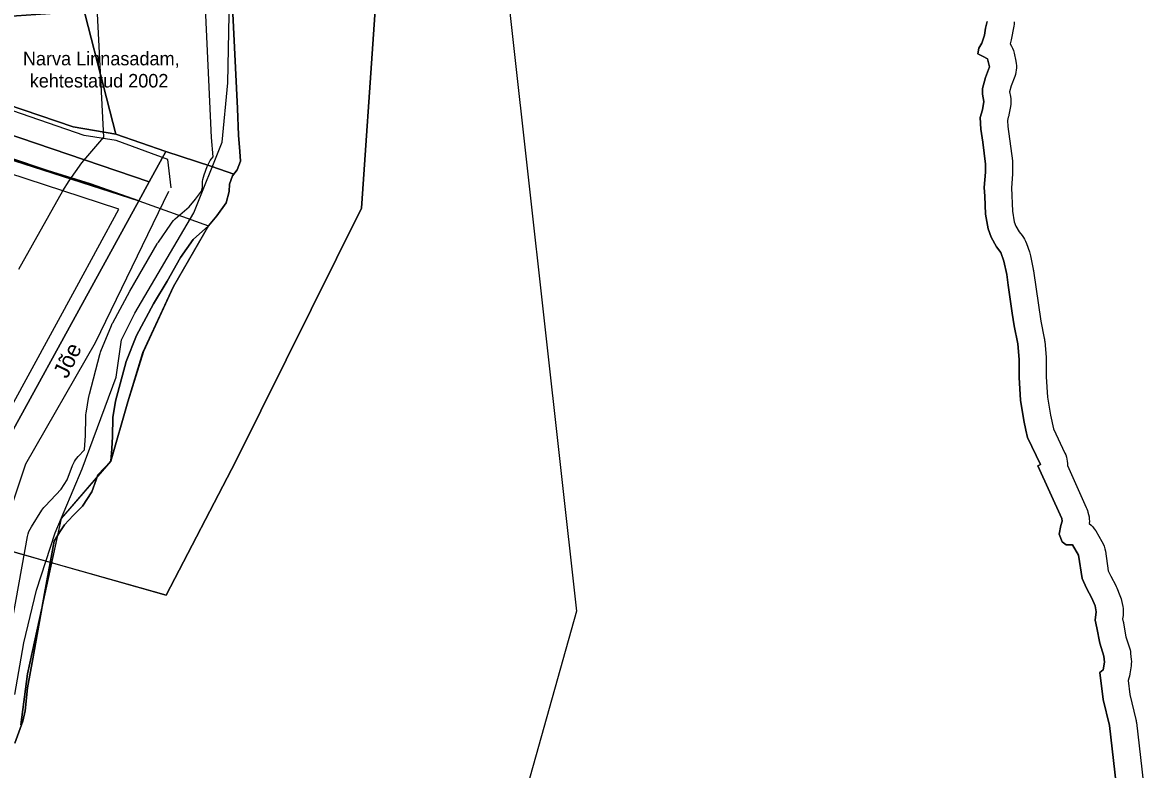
# Model space of a CAD drawing. Extents: x 728832 to 739469, y 6586263 to 6599699.
# Drawn here: x 738858.8 to 739275, y 6589907.2 to 6590183.4 of the extents above; entities that cross this region are included whole.
import ezdxf

# ---------------------------------------------------------------- set-up
doc = ezdxf.new("R2010")
doc.units = 0
for name, color, linetype in [('a_kalda_ekv', 7, 'Continuous'), ('a_kalda_veekaitsev', 7, 'Continuous'), ('a_looduskaitse_voond', 7, 'Continuous'), ('a_piir', 7, 'Continuous'), ('a_veekogu_piir', 7, 'Continuous'), ('dp_hoonestus', 7, 'Continuous'), ('v_dp_kehtiv', 7, 'Continuous'), ('v_dp_kehtiv_tekst', 7, 'Continuous'), ('v_dp_kontaktvoond', 7, 'Continuous'), ('v_dp_tanav_tekst', 7, 'Continuous'), ('v_olol_transp_jjt', 7, 'Continuous')]:
    doc.layers.add(name, color=color, linetype=linetype)

msp = doc.modelspace()

# ---------------------------------------------------------------- linework, layer by layer
at = {"layer": 'a_kalda_ekv'}
msp.add_lwpolyline([(738857.47, 6590092.24), (738873.8, 6590121.13), (738876.13, 6590124.85), (738880.71, 6590131.52), (738888.96, 6590141.03), (738886.6, 6590186.61), (738884.94, 6590197.52), (738885.19, 6590218.49), (738887.23, 6590228.8), (738886.16, 6590230.66), (738878.79, 6590251.31), (738871.89, 6590262.03), (738871.04, 6590263.97), (738863.76, 6590273.78), (738857.24, 6590285.58)], dxfattribs=at)
at = {"layer": 'a_kalda_veekaitsev'}
for points in [[(738850.87, 6589939.22), (738860.7, 6589993.36), (738860.92, 6589994.29), (738861.22, 6589995.21), (738861.62, 6589996.09), (738862.09, 6589996.92), (738865.96, 6590003.03), (738866.34, 6590003.58), (738866.75, 6590004.1), (738867.2, 6590004.6), (738873.13, 6590010.78), (738875.4, 6590014.34), (738877.35, 6590019.59), (738877.66, 6590020.32), (738878.02, 6590021.03), (738878.43, 6590021.7), (738878.9, 6590022.34), (738879.42, 6590022.94), (738881.73, 6590025.41), (738882.11, 6590030.73), (738882.2, 6590037.42), (738882.22, 6590037.94), (738882.27, 6590038.46), (738882.34, 6590038.97), (738883.39, 6590045.11), (738883.45, 6590045.4), (738883.51, 6590045.69), (738883.58, 6590045.98), (738887.46, 6590060.63), (738887.57, 6590061.03), (738887.71, 6590061.43), (738887.85, 6590061.82), (738891.72, 6590071.38), (738891.86, 6590071.72), (738892.02, 6590072.06), (738892.19, 6590072.39), (738898.52, 6590084.08), (738908.69, 6590101.55), (738908.81, 6590101.77), (738908.95, 6590101.98), (738909.09, 6590102.19), (738913.67, 6590108.86), (738914.18, 6590109.53), (738914.74, 6590110.16), (738915.35, 6590110.73), (738920.46, 6590115.18), (738922.83, 6590118.01), (738925.01, 6590121.06), (738925.36, 6590122.33), (738925.38, 6590123.74), (738925.43, 6590124.57), (738925.55, 6590125.39), (738925.74, 6590126.2), (738925.99, 6590127), (738927.15, 6590130.16), (738927.47, 6590130.91), (738927.84, 6590131.64), (738928.28, 6590132.34), (738928.77, 6590133), (738929.34, 6590133.71), (738928.77, 6590140.91), (738926.54, 6590188.74)], [(738936.53, 6590189.2), (738938.37, 6590151.54), (738938.74, 6590141.69), (738939.18, 6590135.73), (738939.49, 6590132.15), (738938.28, 6590128.86), (738936.54, 6590126.71), (738935.38, 6590123.55), (738935.33, 6590120.89), (738934.18, 6590116.71), (738930.75, 6590111.88), (738927.61, 6590108.15), (738921.91, 6590103.19), (738917.33, 6590096.52), (738912.29, 6590087.76), (738907.32, 6590079.32), (738900.99, 6590067.63), (738897.13, 6590058.07), (738893.25, 6590043.42), (738892.2, 6590037.28), (738892.1, 6590030.3), (738891.83, 6590025.75), (738891.45, 6590021.17), (738886.73, 6590016.11), (738886.1, 6590014.31), (738884.41, 6590009.86), (738881.03, 6590004.57), (738877.54, 6590001.07), (738874.41, 6589997.67), (738872.68, 6589995.03), (738870.54, 6589991.57), (738867, 6589972.26), (738862.7, 6589948.13), (738860.71, 6589937.44), (738859.77, 6589928.86), (738858.93, 6589925.05), (738855.98, 6589916.9)], [(739265.09, 6589887.82), (739260.98, 6589923.4), (739258.66, 6589933.13), (739257.42, 6589943.08), (739258.64, 6589944), (739259.06, 6589946.92), (739258.84, 6589949.11), (739257.33, 6589953.89), (739256.33, 6589959.53), (739255.66, 6589962.39), (739256.06, 6589965.48), (739255.61, 6589967.69), (739254.43, 6589970.5), (739252.45, 6589974.25), (739250.84, 6589977.75), (739249.54, 6589986.39), (739247.23, 6589990.31), (739244.92, 6589990.21), (739243.51, 6589991.42), (739242.4, 6589994.23), (739243.01, 6589997.45), (739243.51, 6589999.06), (739243.28, 6590000), (739234.48, 6590019.44), (739235.41, 6590019.9), (739230.64, 6590029.89), (739230.05, 6590032.66), (739229.33, 6590036.28), (739228.04, 6590043.73), (739227.55, 6590052.13), (739227.56, 6590058.75), (739227.05, 6590064.58), (739225.65, 6590071.21), (739224.94, 6590075.86), (739223.48, 6590086.24), (739222.94, 6590090.16), (739221.93, 6590095.19), (739220.8, 6590098.37), (739219.18, 6590100.41), (739217.2, 6590103.95), (739216.05, 6590107.13), (739215.08, 6590112.51), (739214.83, 6590119.12), (739214.63, 6590122.39), (739215.07, 6590128.04), (739215.13, 6590130.96), (739214.09, 6590139.18), (739213.39, 6590143.98), (739213.1, 6590148.21), (739213.92, 6590151.07), (739214.51, 6590154.19), (739214.01, 6590156.83), (739213.96, 6590158.99), (739215.06, 6590163.04), (739216.52, 6590166.93), (739215.86, 6590169.97), (739214.21, 6590170.78), (739212.26, 6590171.77), (739212.65, 6590173.9), (739213.7, 6590175.76), (739214.77, 6590178.7), (739215.15, 6590181.33), (739215.69, 6590183.77)], [(739225.69, 6590183.66), (739225.64, 6590182.82), (739225.53, 6590182), (739224.61, 6590176.93), (739224.51, 6590176.43), (739224.38, 6590175.94), (739224.23, 6590175.45), (739224.7, 6590174.66), (739225.09, 6590173.83), (739225.4, 6590172.97), (739225.64, 6590172.08), (739226.29, 6590169.04), (739226.43, 6590168.24), (739226.5, 6590167.43), (739226.51, 6590166.61), (739226.45, 6590165.8), (739226.33, 6590165), (739226.14, 6590164.21), (739225.89, 6590163.44), (739224.59, 6590159.97), (739224.01, 6590157.8), (739224.34, 6590156.03), (739224.47, 6590155.11), (739224.51, 6590154.17), (739224.47, 6590153.24), (739224.33, 6590152.32), (739223.74, 6590149.2), (739223.68, 6590148.91), (739223.61, 6590148.62), (739223.53, 6590148.33), (739223.2, 6590147.15), (739223.34, 6590144.98), (739225.04, 6590132.28), (739225.1, 6590131.78), (739225.13, 6590131.27), (739225.13, 6590130.75), (739225.07, 6590127.84), (739225.06, 6590127.65), (739225.05, 6590127.46), (739225.04, 6590127.26), (739224.65, 6590122.23), (739225.04, 6590113.63), (739225.74, 6590109.74), (739226.33, 6590108.12), (739227.51, 6590106), (739228.63, 6590104.59), (739229.11, 6590103.93), (739229.54, 6590103.22), (739229.91, 6590102.48), (739230.22, 6590101.72), (739231.35, 6590098.54), (739231.5, 6590098.09), (739231.63, 6590097.63), (739231.73, 6590097.16), (739232.74, 6590092.14), (739232.78, 6590091.95), (739232.81, 6590091.77), (739232.84, 6590091.58), (739235.5, 6590072.95), (739236.83, 6590066.64), (739236.91, 6590066.24), (739236.97, 6590065.85), (739237.01, 6590065.45), (739237.52, 6590059.63), (739237.54, 6590059.33), (739237.56, 6590059.04), (739237.56, 6590058.74), (739237.55, 6590052.41), (739237.99, 6590044.87), (739239.16, 6590038.14), (739240.19, 6590033.1), (739244.44, 6590024.21), (739244.75, 6590023.48), (739245.01, 6590022.72), (739245.2, 6590021.94), (739245.34, 6590021.16), (739245.4, 6590020.36), (739245.41, 6590019.56), (739252.39, 6590004.12), (739252.63, 6590003.55), (739252.83, 6590002.97), (739252.99, 6590002.38), (739253.22, 6590001.44), (739253.39, 6590000.62), (739253.48, 6589999.79), (739253.51, 6589998.96), (739253.47, 6589998.13), (739254.15, 6589997.53), (739254.78, 6589996.87), (739255.35, 6589996.15), (739255.85, 6589995.39), (739258.16, 6589991.47), (739258.6, 6589990.62), (739258.96, 6589989.73), (739259.24, 6589988.82), (739259.43, 6589987.88), (739260.52, 6589980.64), (739261.42, 6589978.68), (739263.27, 6589975.17), (739263.4, 6589974.91), (739263.53, 6589974.65), (739263.65, 6589974.38), (739264.83, 6589971.58), (739265.06, 6589970.96), (739265.26, 6589970.33), (739265.41, 6589969.69), (739265.86, 6589967.48), (739265.99, 6589966.66), (739266.06, 6589965.83), (739266.05, 6589965), (739265.98, 6589964.17), (739265.81, 6589962.9), (739266.06, 6589961.81), (739266.1, 6589961.64), (739266.14, 6589961.46), (739266.17, 6589961.29), (739267.06, 6589956.29), (739268.38, 6589952.12), (739268.56, 6589951.46), (739268.7, 6589950.79), (739268.79, 6589950.11), (739269.01, 6589947.92), (739269.06, 6589947.11), (739269.04, 6589946.3), (739268.96, 6589945.49), (739268.54, 6589942.58), (739268.38, 6589941.75), (739268.16, 6589940.93), (739267.86, 6589940.14), (739268.52, 6589934.92), (739270.71, 6589925.72), (739270.8, 6589925.33), (739270.86, 6589924.94), (739270.92, 6589924.55), (739275.02, 6589888.97)]]:
    msp.add_lwpolyline(points, dxfattribs=at)
at = {"layer": 'a_looduskaitse_voond'}
msp.add_lwpolyline([(738848.75, 6590030.6), (738861.66, 6590054.1), (738878.87, 6590085.71), (738894.43, 6590114.34), (738853.38, 6590127.75)], dxfattribs=at)
at = {"layer": 'a_piir'}
for points in [[(738618.75, 6590380.33), (738607.64, 6590378.6), (738566.13, 6590357.93), (738559.92, 6590348.55), (738569.64, 6590329.09), (738573.98, 6590313.62), (738617.27, 6590348.72), (738629.02, 6590355.8), (738689.32, 6590229.61), (738675.68, 6590194.79), (738695.6, 6590176.04), (738728.46, 6590145.13), (738765.47, 6590163.01), (738835.3, 6590138.74), (738883.93, 6590123.77), (738901.84, 6590117.49), (738905.68, 6590124.48), (738762.03, 6590173.28), (738749.36, 6590180.65), (738732, 6590194.18), (738718.81, 6590211.81), (738712.34, 6590224.93), (738650.22, 6590356.38), (738637.19, 6590372.44)], [(738843.25, 6590304.19), (738738, 6590297.5), (738693.54, 6590289.26), (738721.83, 6590229.41), (738728.22, 6590217.92), (738736.09, 6590207.4), (738745.32, 6590197.99), (738755.65, 6590189.94), (738767, 6590183.31), (738779.12, 6590178.25), (738877.58, 6590144.8), (738893.32, 6590142.09), (738861.55, 6590265.91)]]:
    msp.add_lwpolyline(points, close=True, dxfattribs=at)
for points in [[(738861.55, 6590265.91), (738893.32, 6590142.09), (738911.86, 6590135.74), (738928.88, 6590130.08), (738937.06, 6590127.35), (738938.28, 6590128.86), (738939.49, 6590132.15), (738939.18, 6590135.73), (738938.74, 6590141.69), (738938.37, 6590151.54), (738936.53, 6590189.2)], [(738762.03, 6590173.28), (738905.68, 6590124.48), (738911.86, 6590135.74), (738893.32, 6590142.09), (738877.58, 6590144.8), (738779.12, 6590178.25)], [(738833.77, 6589993.69), (738901.84, 6590117.49), (738883.93, 6590123.77), (738835.3, 6590138.74)], [(738858.18, 6589923.69), (738860.66, 6589942.56), (738873.24, 6589999.99), (738891.45, 6590021.17), (738897.74, 6590043.18), (738903.36, 6590061.39), (738914.63, 6590085.72), (738927.61, 6590108.15), (738930.75, 6590111.88), (738934.15, 6590116.67), (738935.33, 6590120.89), (738935.38, 6590123.55), (738936.54, 6590126.71), (738937.06, 6590127.35), (738928.88, 6590130.08), (738911.86, 6590135.74), (738905.68, 6590124.48), (738901.84, 6590117.49), (738833.77, 6589993.69)]]:
    msp.add_lwpolyline(points, dxfattribs=at)
at = {"layer": 'a_veekogu_piir'}
for points in [[(738855.98, 6589916.9), (738858.93, 6589925.05), (738859.77, 6589928.86), (738860.71, 6589937.44), (738862.7, 6589948.13), (738867, 6589972.26), (738870.54, 6589991.57), (738872.68, 6589995.03), (738874.41, 6589997.67), (738877.54, 6590001.07), (738881.03, 6590004.57), (738884.41, 6590009.86), (738886.1, 6590014.31), (738886.73, 6590016.11), (738891.45, 6590021.17), (738891.83, 6590025.75), (738892.1, 6590030.3), (738892.2, 6590037.28), (738893.25, 6590043.42), (738897.13, 6590058.07), (738900.99, 6590067.63), (738907.32, 6590079.32), (738912.29, 6590087.76), (738917.33, 6590096.52), (738921.91, 6590103.19), (738927.61, 6590108.15), (738930.75, 6590111.88), (738934.18, 6590116.71), (738935.33, 6590120.89), (738935.38, 6590123.55), (738936.54, 6590126.71), (738938.28, 6590128.86), (738939.49, 6590132.15), (738939.18, 6590135.73), (738938.74, 6590141.69), (738938.37, 6590151.54), (738936.53, 6590189.2)], [(739215.69, 6590183.77), (739215.15, 6590181.33), (739214.77, 6590178.7), (739213.7, 6590175.76), (739212.65, 6590173.9), (739212.26, 6590171.77), (739214.21, 6590170.78), (739215.86, 6590169.97), (739216.52, 6590166.93), (739215.06, 6590163.04), (739213.96, 6590158.99), (739214.01, 6590156.83), (739214.51, 6590154.19), (739213.92, 6590151.07), (739213.1, 6590148.21), (739213.39, 6590143.98), (739214.09, 6590139.18), (739215.13, 6590130.96), (739215.07, 6590128.04), (739214.63, 6590122.39), (739214.83, 6590119.12), (739215.08, 6590112.51), (739216.05, 6590107.13), (739217.2, 6590103.95), (739219.18, 6590100.41), (739220.8, 6590098.37), (739221.93, 6590095.19), (739222.94, 6590090.16), (739223.48, 6590086.24), (739224.94, 6590075.86), (739225.65, 6590071.21), (739227.05, 6590064.58), (739227.56, 6590058.75), (739227.55, 6590052.13), (739228.04, 6590043.73), (739229.33, 6590036.28), (739230.05, 6590032.66), (739230.64, 6590029.89), (739235.41, 6590019.9), (739234.48, 6590019.44), (739243.28, 6590000), (739243.51, 6589999.06), (739243.01, 6589997.45), (739242.4, 6589994.23), (739243.51, 6589991.42), (739244.92, 6589990.21), (739247.23, 6589990.31), (739249.54, 6589986.39), (739250.84, 6589977.75), (739252.45, 6589974.25), (739254.43, 6589970.5), (739255.61, 6589967.69), (739256.06, 6589965.48), (739255.66, 6589962.39), (739256.33, 6589959.53), (739257.33, 6589953.89), (739258.84, 6589949.11), (739259.06, 6589946.92), (739258.64, 6589944), (739257.42, 6589943.08), (739258.66, 6589933.13), (739260.98, 6589923.4), (739265.09, 6589887.82)]]:
    msp.add_lwpolyline(points, dxfattribs=at)
at = {"layer": 'dp_hoonestus'}
for points in [[(738544.55, 6591130.54), (738777.58, 6590706.02), (738824.58, 6590644.12), (738867.62, 6590606.55), (738942.09, 6590474.98), (739017.23, 6590295.07), (739034.11, 6590232.51), (739063.74, 6589965.72), (739039.57, 6589879.66), (738995.22, 6589833.98), (738899.89, 6589713.66), (738848.75, 6589599.46), (738792.31, 6589420.72)], [(738544.55, 6591130.54), (738777.58, 6590706.02), (738824.58, 6590644.12), (738867.62, 6590606.55), (738942.09, 6590474.98), (739017.23, 6590295.07), (739034.11, 6590232.51), (739063.74, 6589965.72), (739039.57, 6589879.66), (738995.22, 6589833.98), (738899.89, 6589713.66), (738848.75, 6589599.46), (738792.31, 6589420.72)], [(738856.03, 6589934.94), (738859.34, 6589953.97), (738863.97, 6589973.5), (738870.93, 6589994.68), (738880.86, 6590018.35), (738893.43, 6590052.28), (738895.42, 6590066.02), (738900.39, 6590075.95), (738922.23, 6590113.02), (738932.66, 6590139.17), (738934.81, 6590161.02), (738935.31, 6590186.17), (738936.13, 6590214.47), (738933.32, 6590236.65), (738921.24, 6590274.55), (738915.28, 6590280.18), (738914.45, 6590286.96), (738899.23, 6590307.32), (738878.54, 6590338.77), (738865.96, 6590358.13), (738851.06, 6590395.2)], [(738856.03, 6589934.94), (738859.34, 6589953.97), (738863.97, 6589973.5), (738870.93, 6589994.68), (738880.86, 6590018.35), (738893.43, 6590052.28), (738895.42, 6590066.02), (738900.39, 6590075.95), (738922.23, 6590113.02), (738932.66, 6590139.17), (738934.81, 6590161.02), (738935.31, 6590186.17), (738936.13, 6590214.47), (738933.32, 6590236.65), (738921.24, 6590274.55), (738915.28, 6590280.18), (738914.45, 6590286.96), (738899.23, 6590307.32), (738878.54, 6590338.77), (738865.96, 6590358.13), (738851.06, 6590395.2)]]:
    msp.add_lwpolyline(points, dxfattribs=at)
at = {"layer": 'v_dp_kehtiv'}
for points in [[(738834.26, 6590139.1), (738901.84, 6590117.49), (738833.77, 6589993.69), (738849.37, 6589989.36), (738911.94, 6589971.59), (738937.72, 6590021.18), (738984.2, 6590114.69), (738993.34, 6590247.02), (738942.21, 6590350.94), (738908.53, 6590414.77), (738868.42, 6590397.1), (738843.38, 6590385.47), (738811.42, 6590370.68), (738843.25, 6590304.19), (738861.55, 6590265.91), (738881.66, 6590187.51), (738849.36, 6590185.31)], [(738833.77, 6589993.69), (738901.84, 6590117.49), (738834.26, 6590139.1), (738849.36, 6590185.31), (738881.66, 6590187.51), (738861.55, 6590265.91), (738843.25, 6590304.19), (738811.42, 6590370.68), (738868.42, 6590397.1), (738908.53, 6590414.77), (738942.21, 6590350.94), (738993.34, 6590247.02), (738984.2, 6590114.69), (738937.72, 6590021.18), (738911.94, 6589971.59), (738869.57, 6589983.62), (738849.37, 6589989.36)]]:
    msp.add_lwpolyline(points, close=True, dxfattribs=at)
at = {"layer": 'v_dp_kontaktvoond'}
msp.add_lwpolyline([(738765.47, 6590163.01), (738901.84, 6590117.49), (738927.61, 6590108.15), (738914.71, 6590085.81), (738903.53, 6590061.76), (738897.74, 6590043.18), (738891.45, 6590021.17), (738873.14, 6590000.04), (738860.63, 6589942.5), (738858.24, 6589923.73)], dxfattribs=at)
at = {"layer": 'v_olol_transp_jjt'}
for points in [[(738913.83, 6590122.24), (738912.56, 6590132.76), (738893.48, 6590139.7), (738881.68, 6590141.55), (738768.41, 6590180.71), (738753.8, 6590188.84), (738743.64, 6590197.42), (738734.87, 6590206), (738726.51, 6590216.87), (738721.42, 6590223.76), (738654.4, 6590367.7), (738643.42, 6590381.67), (738621.61, 6590391.85)], [(738701.22, 6589304.96), (738722.43, 6589361.21), (738744.16, 6589429.66), (738746.01, 6589438.06), (738752.32, 6589484.93), (738757.68, 6589561.53), (738761.22, 6589598.39), (738763.23, 6589614.26), (738774.35, 6589665.72), (738786.24, 6589707.98), (738799.01, 6589743.38), (738822.48, 6589793.3), (738827.95, 6589808.63), (738827.95, 6589817.5), (738830.43, 6589848.34), (738832.8, 6589864.39), (738836.51, 6589886.76), (738847.81, 6589938.4), (738851.48, 6589981.51), (738853.67, 6590001.03), (738860.07, 6590020.16), (738885.77, 6590065.05), (738912.97, 6590120.99)]]:
    msp.add_lwpolyline(points, dxfattribs=at)

# ---------------------------------------------------------------- texts
at = {"layer": 'v_dp_kehtiv_tekst'}
for s, p in [('Narva Linnasadam,', (738858.97, 6590167.54)), ('kehtestatud 2002', (738861.49, 6590159.35))]:
    msp.add_text(s, height=5, dxfattribs=at).set_placement(p)
at = {"layer": 'v_dp_tanav_tekst'}
msp.add_text('Jõe', height=6, rotation=64.3329, dxfattribs=at).set_placement((738875.32, 6590051.39))

doc.saveas('drawing.dxf')
